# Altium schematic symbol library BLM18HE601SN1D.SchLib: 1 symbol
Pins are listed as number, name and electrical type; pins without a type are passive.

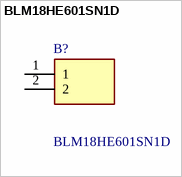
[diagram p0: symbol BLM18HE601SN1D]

## BLM18HE601SN1D
designator B?
BLM18_N1D Series EMI Suppression Filter 600+/-25% at 100MHz 800mA @85; Manufacturer_Name: Murata Electronics; Geometry.Height: 0.95mm
footprint BLM18SP221SN1B
pins: 1, 2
